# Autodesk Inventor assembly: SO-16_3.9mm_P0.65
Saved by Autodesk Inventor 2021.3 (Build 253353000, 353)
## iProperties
Created: 2022-06
Part Number: SO-16_3.9mm_P0.65
Document SubType Name: Assembly
Designer: Administrator
Title: SO-16_3.9mm_P0.65
Author: Administrator
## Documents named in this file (2)
- c:\worker\convert-fusion-r03\tmp\job-1\203\output\files\98ba3c1f-9f0e-47fe-8659-38db50984f0d\SO-16_3.9mm_P0.65.iam
- c:\worker\convert-fusion-r03\tmp\job-1\203\output\files\98ba3c1f-9f0e-47fe-8659-38db50984f0d\COMPOUND (3).ipt
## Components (1 placed, 1 different names)
1. COMPOUND (3):1
